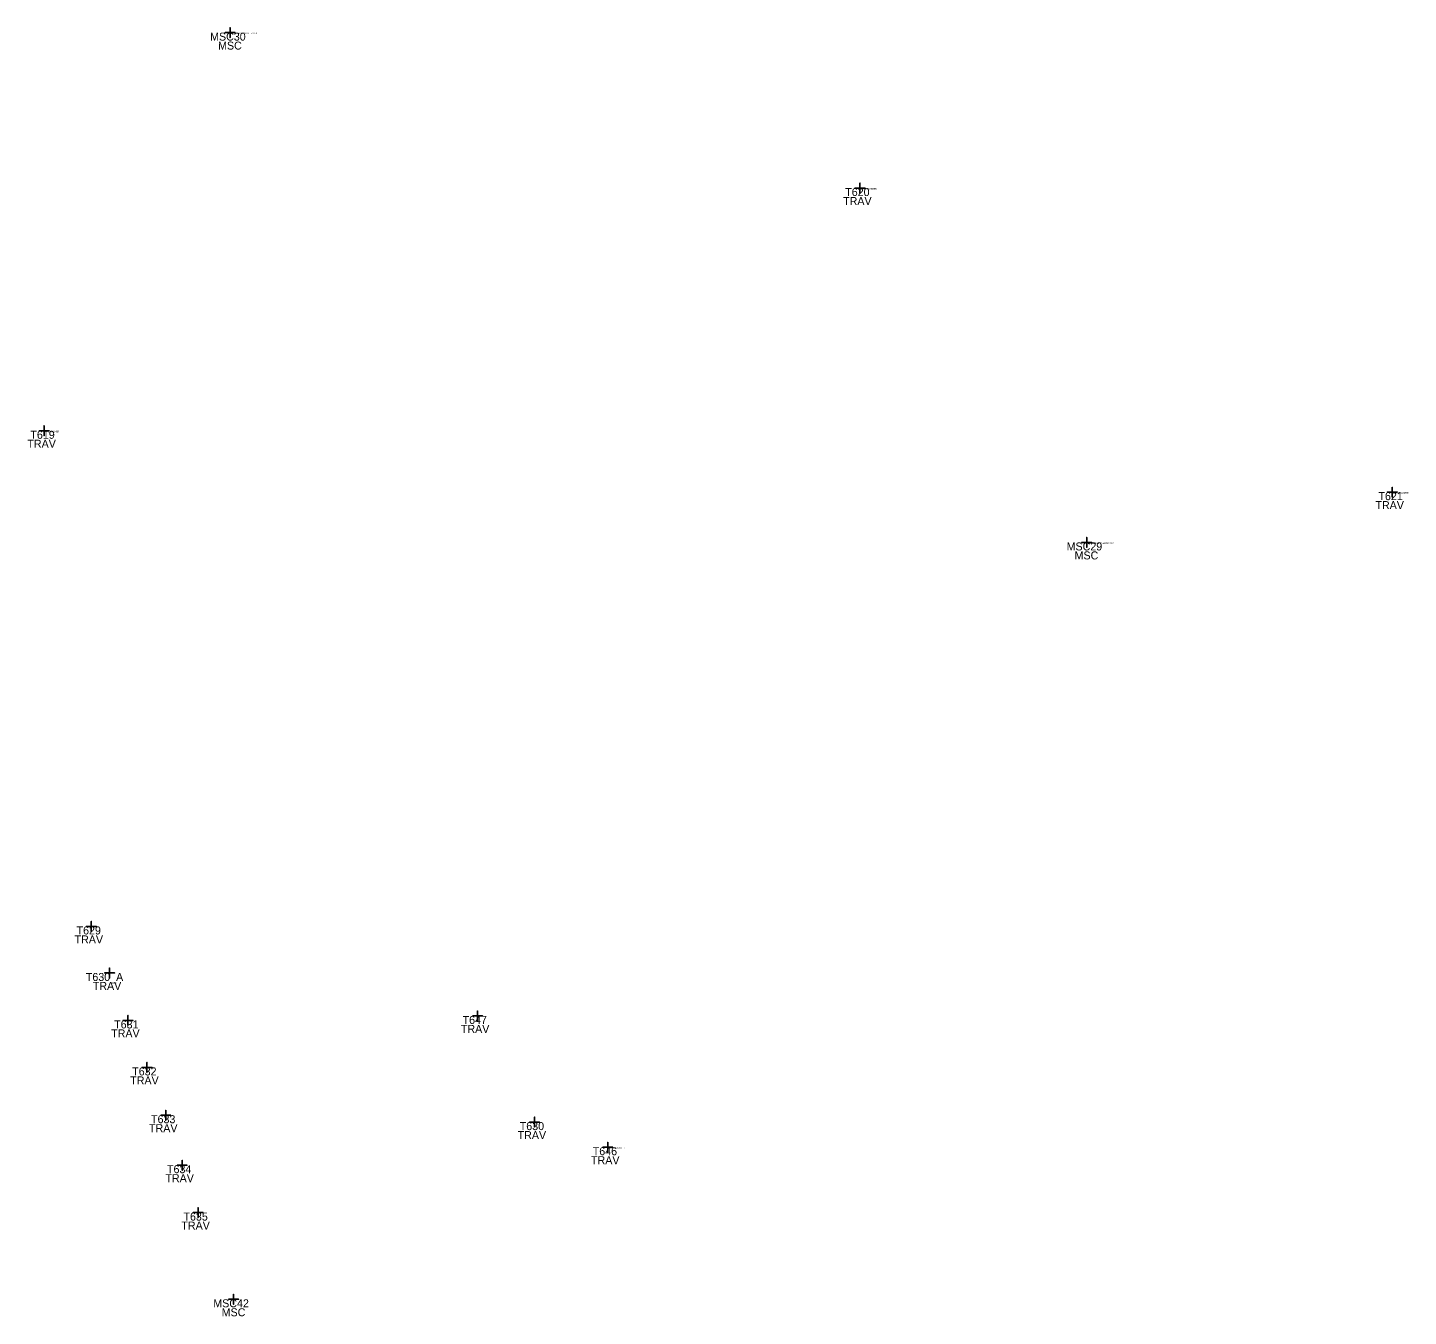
# Model space of a CAD drawing. Extents: x 2342247 to 2353588, y 365809 to 372747.
# Drawn here: x 2346281 to 2347666, y 368468 to 369760 of the extents above; entities that cross this region are included whole.
import ezdxf

# ---------------------------------------------------------------- set-up
doc = ezdxf.new("R2010")
doc.units = 0
for name, color, linetype in [('Level 63', 7, 'Continuous'), ('SV_Control_CP_Code', 7, 'Continuous'), ('SV_Control_CP_Name', 7, 'Continuous'), ('SV_Control_CP_Shot', 7, 'Continuous')]:
    doc.layers.add(name, color=color, linetype=linetype)

msp = doc.modelspace()

# ---------------------------------------------------------------- linework, layer by layer
at = {"layer": 'SV_Control_CP_Shot'}
for points in [[(2346484.3, 369754.8), (2346484.3, 369759.8), (2346484.3, 369754.8), (2346479.3, 369754.8), (2346484.3, 369754.8), (2346484.3, 369749.8), (2346484.3, 369754.8), (2346489.3, 369754.8)], [(2347115.8, 369599), (2347115.8, 369604), (2347115.8, 369599), (2347110.8, 369599), (2347115.8, 369599), (2347115.8, 369594), (2347115.8, 369599), (2347120.8, 369599)], [(2346297.8, 369355.7), (2346297.8, 369360.7), (2346297.8, 369355.7), (2346292.8, 369355.7), (2346297.8, 369355.7), (2346297.8, 369350.7), (2346297.8, 369355.7), (2346302.8, 369355.7)], [(2347649.6, 369294.2), (2347649.6, 369299.2), (2347649.6, 369294.2), (2347644.6, 369294.2), (2347649.6, 369294.2), (2347649.6, 369289.2), (2347649.6, 369294.2), (2347654.6, 369294.2)], [(2347343.2, 369243.8), (2347343.2, 369248.8), (2347343.2, 369243.8), (2347338.2, 369243.8), (2347343.2, 369243.8), (2347343.2, 369238.8), (2347343.2, 369243.8), (2347348.2, 369243.8)], [(2346345.1, 368858.9), (2346345.1, 368863.9), (2346345.1, 368858.9), (2346340.1, 368858.9), (2346345.1, 368858.9), (2346345.1, 368853.9), (2346345.1, 368858.9), (2346350.1, 368858.9)], [(2346363.4, 368812.3), (2346363.4, 368817.3), (2346363.4, 368812.3), (2346358.4, 368812.3), (2346363.4, 368812.3), (2346363.4, 368807.3), (2346363.4, 368812.3), (2346368.4, 368812.3)], [(2346381.8, 368764.7), (2346381.8, 368769.7), (2346381.8, 368764.7), (2346376.8, 368764.7), (2346381.8, 368764.7), (2346381.8, 368759.7), (2346381.8, 368764.7), (2346386.8, 368764.7)], [(2346732.5, 368769.2), (2346732.5, 368774.2), (2346732.5, 368769.2), (2346727.5, 368769.2), (2346732.5, 368769.2), (2346732.5, 368764.2), (2346732.5, 368769.2), (2346737.5, 368769.2)], [(2346400.9, 368717.6), (2346400.9, 368722.6), (2346400.9, 368717.6), (2346395.9, 368717.6), (2346400.9, 368717.6), (2346400.9, 368712.6), (2346400.9, 368717.6), (2346405.9, 368717.6)], [(2346419.8, 368669.7), (2346419.8, 368674.7), (2346419.8, 368669.7), (2346414.8, 368669.7), (2346419.8, 368669.7), (2346419.8, 368664.7), (2346419.8, 368669.7), (2346424.8, 368669.7)], [(2346789.5, 368662.8), (2346789.5, 368667.8), (2346789.5, 368662.8), (2346784.5, 368662.8), (2346789.5, 368662.8), (2346789.5, 368657.8), (2346789.5, 368662.8), (2346794.5, 368662.8)], [(2346863, 368637.6), (2346863, 368642.6), (2346863, 368637.6), (2346858, 368637.6), (2346863, 368637.6), (2346863, 368632.6), (2346863, 368637.6), (2346868, 368637.6)], [(2346436.2, 368619.6), (2346436.2, 368624.6), (2346436.2, 368619.6), (2346431.2, 368619.6), (2346436.2, 368619.6), (2346436.2, 368614.6), (2346436.2, 368619.6), (2346441.2, 368619.6)], [(2346452.2, 368572.1), (2346452.2, 368577.1), (2346452.2, 368572.1), (2346447.2, 368572.1), (2346452.2, 368572.1), (2346452.2, 368567.1), (2346452.2, 368572.1), (2346457.2, 368572.1)], [(2346487.8, 368485.2), (2346487.8, 368490.2), (2346487.8, 368485.2), (2346482.8, 368485.2), (2346487.8, 368485.2), (2346487.8, 368480.2), (2346487.8, 368485.2), (2346492.8, 368485.2)]]:
    msp.add_lwpolyline(points, close=True, dxfattribs=at)

# ---------------------------------------------------------------- texts
at = {"layer": 'Level 63'}
for s, p in [('#5 REBAR W/ PLASTIC CAP', (2346484.3, 369753.3)), ('NAIL W/WASHER', (2347115.8, 369597.5)), ('PK W/WASHER', (2346297.8, 369354.2)), ('NAIL W/WASHER', (2347649.6, 369292.7)), ('#5 REBAR W/ PLASTIC CAP', (2347343.2, 369242.3)), ('NAIL W/WASHER', (2346863, 368636.1))]:
    msp.add_text(s, height=1.5, dxfattribs=at).set_placement(p)
at = {"layer": 'SV_Control_CP_Code'}
for s, p in [('MSC', (2346472.2, 369737.8)), ('TRAV', (2347099, 369582)), ('TRAV', (2346281, 369338.7)), ('TRAV', (2347632.8, 369277.2)), ('MSC', (2347331.1, 369226.8)), ('TRAV', (2346328.3, 368841.9)), ('TRAV', (2346346.6, 368795.3)), ('TRAV', (2346365, 368747.7)), ('TRAV', (2346715.7, 368752.2)), ('TRAV', (2346384.1, 368700.6)), ('TRAV', (2346403, 368652.7)), ('TRAV', (2346772.6, 368645.8)), ('TRAV', (2346846.2, 368620.6)), ('TRAV', (2346419.4, 368602.6)), ('TRAV', (2346435.4, 368555.1)), ('MSC', (2346475.8, 368468.2))]:
    msp.add_text(s, height=8, dxfattribs=at).set_placement(p)
at = {"layer": 'SV_Control_CP_Name'}
for s, p in [('MSC30', (2346464.2, 369746.8)), ('T620', (2347101.1, 369591)), ('T619', (2346284, 369347.7)), ('T621', (2347635.8, 369286.2)), ('MSC29', (2347323.1, 369235.8)), ('T629', (2346330.3, 368850.9)), ('T630_A', (2346339.6, 368804.3)), ('T631', (2346368, 368756.7)), ('T647', (2346717.4, 368761.2)), ('T632', (2346386.1, 368709.6)), ('T633', (2346405, 368661.7)), ('T630', (2346774.7, 368654.8)), ('T646', (2346847.9, 368629.6)), ('T634', (2346421, 368611.6)), ('T635', (2346437.5, 368564.1)), ('MSC42', (2346467.4, 368477.2))]:
    msp.add_text(s, height=8, dxfattribs=at).set_placement(p)

doc.saveas('drawing.dxf')
